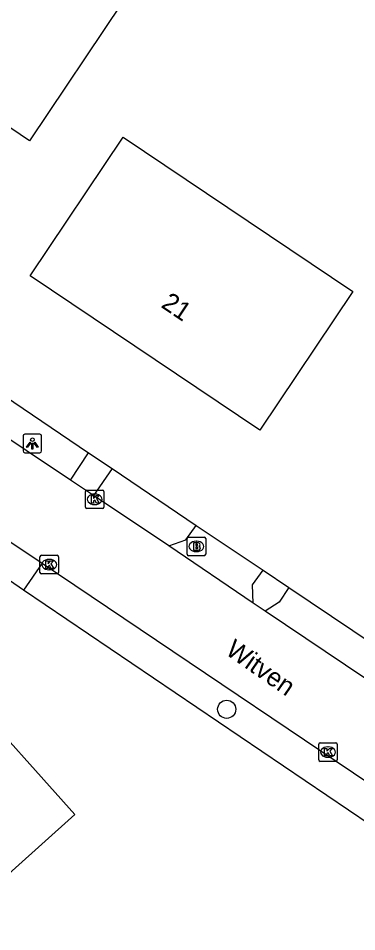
# Model space of a CAD drawing. Extents: x 163268 to 164360, y 381529 to 382285.
# Drawn here: x 164037.29 to 164055.51, y 381849.43 to 381898.55 of the extents above; entities that cross this region are included whole.
import ezdxf

# ---------------------------------------------------------------- set-up
doc = ezdxf.new("R2010")
doc.units = 0
for name, color, linetype in [('IMGEO_Boom', 7, 'Continuous'), ('IMGEO_Brandkraan', 7, 'Continuous'), ('IMGEO_Groenvoorziening', 7, 'Continuous'), ('IMGEO_Kolk', 7, 'Continuous'), ('IMGEO_Lichtpunt', 7, 'Continuous'), ('IMGEO_Openbare_ruimte_label', 7, 'Continuous'), ('IMGEO_Pand', 7, 'Continuous'), ('IMGEO_Pand_nummerreeks', 7, 'Continuous'), ('IMGEO_Rijbaan_lokaal_open', 7, 'Continuous'), ('IMGEO_Voetpad_halfverhard', 7, 'Continuous'), ('IMGEO_Voetpad_open', 7, 'Continuous')]:
    doc.layers.add(name, color=color, linetype=linetype)

msp = doc.modelspace()

# ---------------------------------------------------------------- linework, layer by layer
at = {"layer": 'IMGEO_Boom'}
msp.add_circle((164048.51, 381861.391), 0.489, dxfattribs=at)
at = {"layer": 'IMGEO_Brandkraan'}
for p, q in [((164046.378, 381869.725), (164046.378, 381870.577)), ((164046.453, 381870.651), (164047.305, 381870.651)), ((164046.866, 381870.431), (164046.891, 381870.431)), ((164047.379, 381870.577), (164047.379, 381869.725)), ((164046.889, 381869.871), (164046.864, 381869.871)), ((164047.305, 381869.651), (164046.453, 381869.651))]:
    msp.add_line(p, q, dxfattribs=at)
for points in [[(164046.378, 381869.725), (164046.378, 381870.577)], [(164046.453, 381870.651), (164047.305, 381870.651)], [(164046.726, 381870.351), (164046.726, 381869.951), (164046.939, 381869.951)], [(164046.957, 381870.351), (164046.726, 381870.351)], [(164046.905, 381870.27), (164046.851, 381870.27), (164046.851, 381870.194)], [(164047.379, 381870.577), (164047.379, 381869.725)], [(164046.851, 381870.194), (164046.904, 381870.194)], [(164046.913, 381870.118), (164046.851, 381870.118), (164046.851, 381870.037)], [(164046.851, 381870.037), (164046.913, 381870.037)], [(164047.305, 381869.651), (164046.453, 381869.651)]]:
    msp.add_lwpolyline(points, dxfattribs=at)
for centre, radius, start, end in [((164046.455, 381870.575), 0.0765, 91.552, 178.448), ((164046.455, 381870.575), 0.0765, 91.552, 178.448), ((164046.906, 381870.232), 0.0379, 267.8285, 90.9355), ((164046.961, 381870.206), 0.145, 59.4692, 91.5367), ((164046.986, 381870.253), 0.0922, 285.5137, 58.1501), ((164047.303, 381870.575), 0.0765, 1.552, 88.448), ((164047.303, 381870.575), 0.0765, 1.552, 88.448), ((164046.914, 381870.077), 0.0404, 269.8759, 90.5077), ((164046.945, 381870.202), 0.251, 268.6676, 293.5347), ((164046.991, 381870.061), 0.105, 301.3115, 78.989), ((164046.455, 381869.727), 0.0765, 181.552, 268.448), ((164046.455, 381869.727), 0.0765, 181.552, 268.448), ((164047.303, 381869.727), 0.0765, 271.552, 358.448), ((164047.303, 381869.727), 0.0765, 271.552, 358.448)]:
    msp.add_arc(centre, radius, start, end, dxfattribs=at)
for centre, major_axis, ratio, start_param, end_param in [((164046.865, 381870.151), (-0.387, 0.002), 0.722429, 4.712389, 7.853982), ((164046.89, 381870.151), (-0.39, 0.002), 0.717154, 1.570796, 4.712389)]:
    msp.add_ellipse(centre, major_axis=major_axis, ratio=ratio, start_param=start_param, end_param=end_param, dxfattribs=at)
at = {"layer": 'IMGEO_Groenvoorziening'}
msp.add_lwpolyline([(164037.574, 381867.791), (164036.279, 381868.667)], dxfattribs=at)
at = {"layer": 'IMGEO_Kolk'}
for p, q in [((164040.903, 381872.256), (164040.903, 381873.108)), ((164040.978, 381873.182), (164041.83, 381873.182)), ((164041.391, 381872.962), (164041.416, 381872.962)), ((164041.904, 381873.108), (164041.904, 381872.256)), ((164041.414, 381872.402), (164041.389, 381872.402)), ((164041.83, 381872.182), (164040.978, 381872.182)), ((164038.458, 381868.745), (164038.458, 381869.597)), ((164038.533, 381869.671), (164039.385, 381869.671)), ((164038.946, 381869.451), (164038.971, 381869.451)), ((164039.459, 381869.597), (164039.459, 381868.745)), ((164038.969, 381868.891), (164038.944, 381868.891)), ((164039.385, 381868.671), (164038.533, 381868.671)), ((164053.459, 381858.665), (164053.459, 381859.517)), ((164053.534, 381859.591), (164054.386, 381859.591)), ((164054.46, 381859.517), (164054.46, 381858.665)), ((164053.947, 381859.371), (164053.972, 381859.371)), ((164054.386, 381858.591), (164053.534, 381858.591)), ((164053.97, 381858.811), (164053.945, 381858.811))]:
    msp.add_line(p, q, dxfattribs=at)
for points in [[(164040.903, 381872.256), (164040.903, 381873.108)], [(164040.978, 381873.182), (164041.83, 381873.182)], [(164041.224, 381872.882), (164041.347, 381872.882), (164041.347, 381872.731), (164041.477, 381872.882), (164041.641, 381872.882), (164041.495, 381872.731), (164041.648, 381872.482), (164041.496, 381872.482), (164041.411, 381872.646), (164041.347, 381872.579), (164041.347, 381872.482), (164041.224, 381872.482), (164041.224, 381872.882)], [(164041.904, 381873.108), (164041.904, 381872.256)], [(164041.83, 381872.182), (164040.978, 381872.182)], [(164038.458, 381868.745), (164038.458, 381869.597)], [(164038.533, 381869.671), (164039.385, 381869.671)], [(164038.779, 381869.371), (164038.902, 381869.371), (164038.902, 381869.22), (164039.032, 381869.371), (164039.196, 381869.371), (164039.05, 381869.22), (164039.203, 381868.971), (164039.051, 381868.971), (164038.966, 381869.135), (164038.902, 381869.068), (164038.902, 381868.971), (164038.779, 381868.971), (164038.779, 381869.371)], [(164039.459, 381869.597), (164039.459, 381868.745)], [(164039.385, 381868.671), (164038.533, 381868.671)], [(164053.459, 381858.665), (164053.459, 381859.517)], [(164053.534, 381859.591), (164054.386, 381859.591)], [(164054.46, 381859.517), (164054.46, 381858.665)], [(164053.78, 381859.291), (164053.903, 381859.291), (164053.903, 381859.14), (164054.033, 381859.291), (164054.197, 381859.291), (164054.051, 381859.14), (164054.204, 381858.891), (164054.052, 381858.891), (164053.967, 381859.055), (164053.903, 381858.988), (164053.903, 381858.891), (164053.78, 381858.891), (164053.78, 381859.291)], [(164054.386, 381858.591), (164053.534, 381858.591)]]:
    msp.add_lwpolyline(points, dxfattribs=at)
for centre, start, end in [((164040.98, 381873.106), 91.552, 178.448), ((164040.98, 381873.106), 91.552, 178.448), ((164041.828, 381873.106), 1.552, 88.448), ((164041.828, 381873.106), 1.552, 88.448), ((164040.98, 381872.258), 181.552, 268.448), ((164040.98, 381872.258), 181.552, 268.448), ((164041.828, 381872.258), 271.552, 358.448), ((164041.828, 381872.258), 271.552, 358.448), ((164038.535, 381869.595), 91.552, 178.448), ((164038.535, 381869.595), 91.552, 178.448), ((164039.383, 381869.595), 1.552, 88.448), ((164039.383, 381869.595), 1.552, 88.448), ((164038.535, 381868.747), 181.552, 268.448), ((164038.535, 381868.747), 181.552, 268.448), ((164039.383, 381868.747), 271.552, 358.448), ((164039.383, 381868.747), 271.552, 358.448), ((164053.536, 381859.515), 91.552, 178.448), ((164053.536, 381859.515), 91.552, 178.448), ((164054.384, 381859.515), 1.552, 88.448), ((164054.384, 381859.515), 1.552, 88.448), ((164053.536, 381858.667), 181.552, 268.448), ((164053.536, 381858.667), 181.552, 268.448), ((164054.384, 381858.667), 271.552, 358.448), ((164054.384, 381858.667), 271.552, 358.448)]:
    msp.add_arc(centre, 0.0765, start, end, dxfattribs=at)
for centre, major_axis, ratio, start_param, end_param in [((164041.39, 381872.682), (-0.387, 0.002), 0.722429, 4.712389, 7.853982), ((164041.415, 381872.682), (-0.39, 0.002), 0.717154, 1.570796, 4.712389), ((164038.945, 381869.171), (-0.387, 0.002), 0.722429, 4.712389, 7.853982), ((164038.97, 381869.171), (-0.39, 0.002), 0.717154, 1.570796, 4.712389), ((164053.946, 381859.091), (-0.387, 0.002), 0.722429, 4.712389, 7.853982), ((164053.971, 381859.091), (-0.39, 0.002), 0.717154, 1.570796, 4.712389)]:
    msp.add_ellipse(centre, major_axis=major_axis, ratio=ratio, start_param=start_param, end_param=end_param, dxfattribs=at)
at = {"layer": 'IMGEO_Lichtpunt'}
for p, q in [((164038.453, 381876.188), (164037.645, 381876.188)), ((164038.453, 381876.188), (164037.645, 381876.188)), ((164037.551, 381876.093), (164037.551, 381875.286)), ((164037.551, 381876.093), (164037.551, 381875.286)), ((164038.547, 381875.286), (164038.547, 381876.093)), ((164038.547, 381875.286), (164038.547, 381876.093)), ((164037.645, 381875.192), (164038.453, 381875.192)), ((164037.645, 381875.192), (164038.453, 381875.192))]:
    msp.add_line(p, q, dxfattribs=at)
for points in [[(164037.925, 381875.757), (164037.964, 381875.729), (164037.776, 381875.467), (164037.738, 381875.494), (164037.925, 381875.757)], [(164038.027, 381875.709), (164038.074, 381875.709), (164038.074, 381875.387), (164038.027, 381875.387), (164038.027, 381875.709)], [(164038.137, 381875.729), (164038.175, 381875.756), (164038.362, 381875.494), (164038.323, 381875.466), (164038.137, 381875.729)]]:
    msp.add_lwpolyline(points, dxfattribs=at)
msp.add_circle((164038.05, 381875.891), 0.0994, dxfattribs=at)
for centre, start, end in [((164037.645, 381876.093), 90, 180), ((164037.645, 381876.093), 90, 180), ((164038.453, 381876.093), 0, 90), ((164038.453, 381876.093), 0, 90), ((164037.645, 381875.286), 180, 270), ((164037.645, 381875.286), 180, 270), ((164038.453, 381875.286), 270, 0), ((164038.453, 381875.286), 270, 360)]:
    msp.add_arc(centre, 0.0946, start, end, dxfattribs=at)
at = {"layer": 'IMGEO_Pand'}
for points in [[(164037.896, 381891.966), (164034.254, 381894.419), (164033.352, 381893.083), (164030.901, 381889.438), (164019.028, 381897.367), (164023.776, 381904.477), (164029.353, 381900.753), (164029.639, 381900.562), (164029.561, 381900.446), (164033.786, 381897.625), (164034.263, 381898.34), (164034.38, 381898.262), (164036.22, 381901.017), (164040.727, 381907.767), (164043.97, 381905.601), (164044.632, 381905.16), (164046.453, 381907.876), (164047.906, 381906.901), (164037.896, 381891.966)], [(164055.301, 381883.862), (164050.29, 381876.406), (164037.934, 381884.709), (164042.945, 381892.165), (164055.301, 381883.862)], [(164022.506, 381851.666), (164034.418, 381862.323), (164040.335, 381855.737), (164028.428, 381845.055), (164022.506, 381851.666)]]:
    msp.add_lwpolyline(points, dxfattribs=at)
at = {"layer": 'IMGEO_Rijbaan_lokaal_open'}
for points in [[(164040.101, 381873.72), (164030.485, 381880.129)], [(164041.338, 381872.887), (164040.101, 381873.72)], [(164045.389, 381870.177), (164041.338, 381872.887)], [(164036.893, 381870.385), (164038.576, 381869.252)], [(164049.933, 381867.099), (164045.389, 381870.177)], [(164038.576, 381869.252), (164061.479, 381853.831)], [(164050.572, 381866.67), (164049.933, 381867.099)], [(164055.995, 381863.023), (164050.572, 381866.67)]]:
    msp.add_lwpolyline(points, dxfattribs=at)
at = {"layer": 'IMGEO_Voetpad_halfverhard'}
for points in [[(164030.999, 381881.988), (164041.078, 381875.19)], [(164042.347, 381874.343), (164046.869, 381871.277)], [(164038.576, 381869.252), (164037.574, 381867.791)], [(164050.464, 381868.875), (164051.85, 381867.938)], [(164060.897, 381852.025), (164037.574, 381867.791)]]:
    msp.add_lwpolyline(points, dxfattribs=at)
at = {"layer": 'IMGEO_Voetpad_open'}
for points in [[(164040.101, 381873.72), (164041.078, 381875.19)], [(164041.078, 381875.19), (164042.347, 381874.343)], [(164042.347, 381874.343), (164041.338, 381872.887)], [(164045.389, 381870.177), (164046.313, 381870.513), (164046.869, 381871.277)], [(164046.869, 381871.277), (164050.464, 381868.875)], [(164049.933, 381867.099), (164049.906, 381868.076), (164050.464, 381868.875)], [(164051.85, 381867.938), (164051.339, 381867.16), (164050.572, 381866.67)], [(164051.85, 381867.938), (164056.445, 381864.849)]]:
    msp.add_lwpolyline(points, dxfattribs=at)

# ---------------------------------------------------------------- texts
at = {"layer": 'IMGEO_Openbare_ruimte_label'}
msp.add_text('Witven', height=1, rotation=325.1816, dxfattribs=at).set_placement((164048.384, 381864.392))
at = {"layer": 'IMGEO_Pand_nummerreeks'}
msp.add_text('21', height=1, rotation=326.0997, dxfattribs=at).set_placement((164044.926, 381883.047))

doc.saveas('drawing.dxf')
